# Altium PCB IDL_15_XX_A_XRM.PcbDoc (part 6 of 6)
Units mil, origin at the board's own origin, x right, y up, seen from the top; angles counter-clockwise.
Board outline 6653.34 x 6653.34 mil, 6 copper layers (Top Layer - SIG1, Layer 2 - GND1, Layer 3 - PWR, Layer 4 - PWR, Layer 5 - GND2, Bottom Layer - SIG4), stack 59.843 mil thick; 613 components, 324 nets, 1673 pads, 2316 vias.
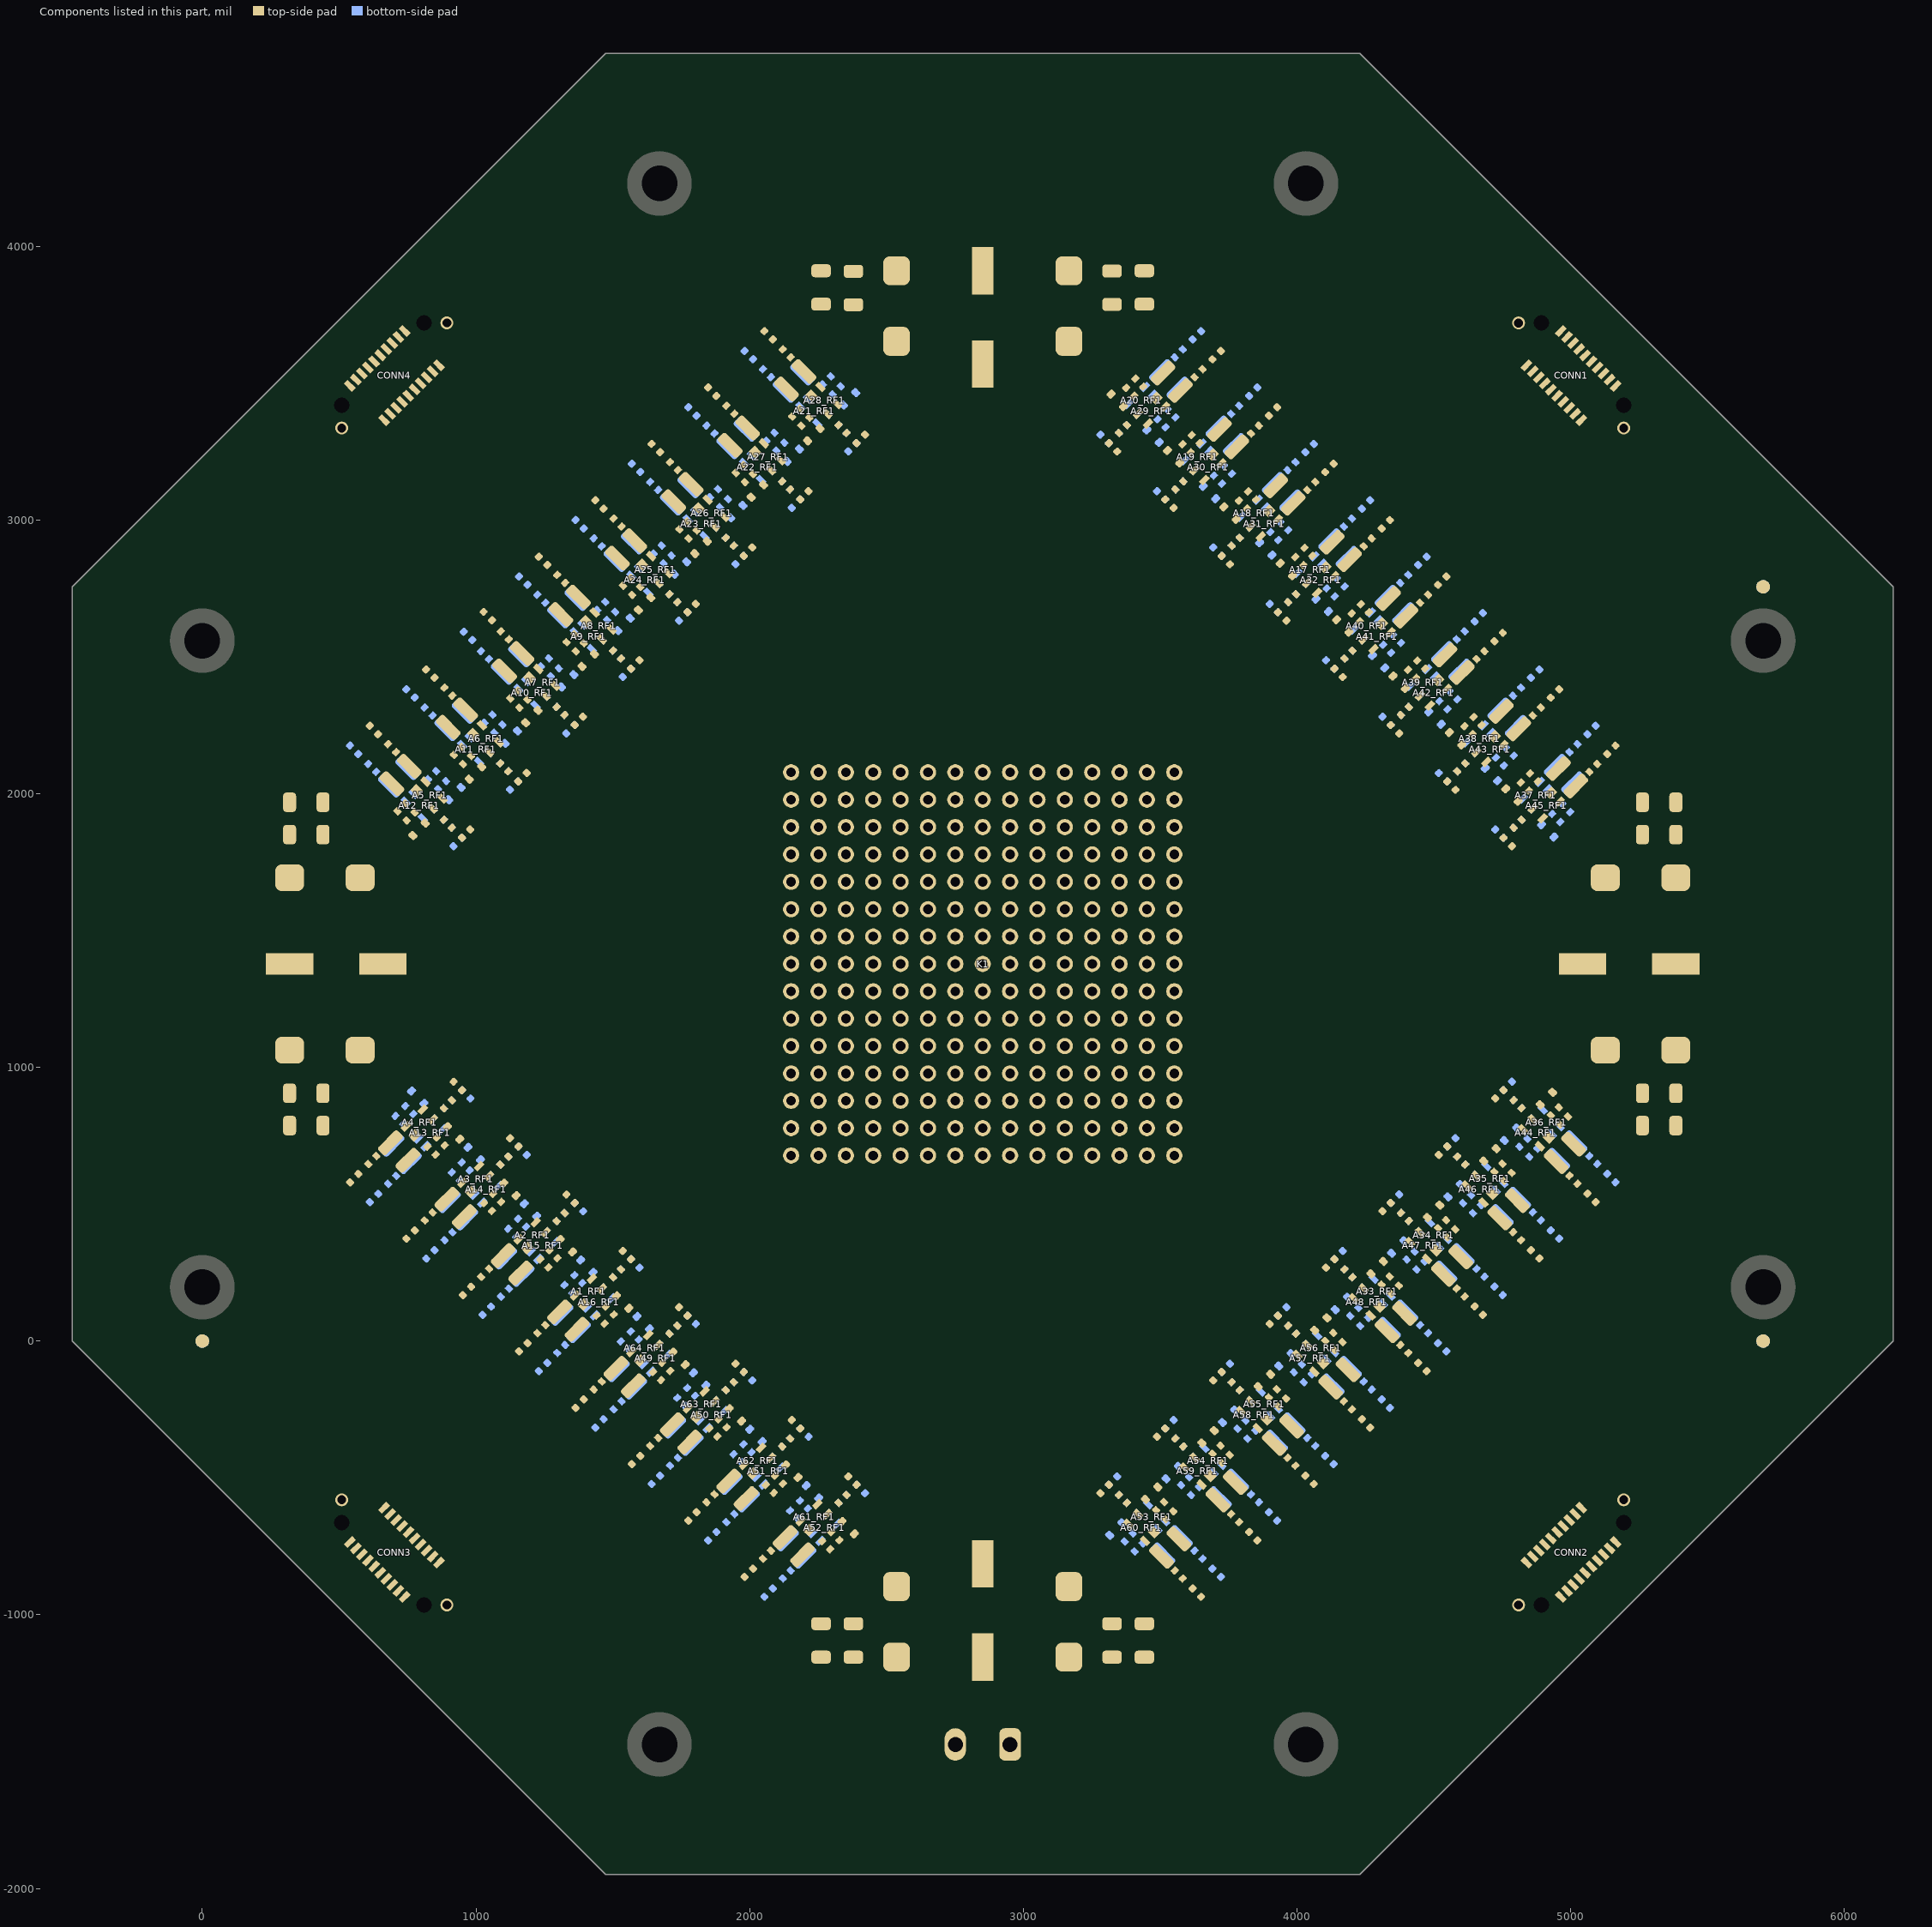
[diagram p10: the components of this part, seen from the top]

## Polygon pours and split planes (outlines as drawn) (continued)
GND on Bottom Layer - SIG4 "L2-GND" (solid, remove dead copper, pour order 38): 1473.48,4704.63 4229.39,4704.63 6178.11,2755.91 6178.11,7.87 6178.11,0 6178.1,0 4229.39,-1948.72 1473.48,-1948.72 -475.24,0 -475.24,2755.9 -475.24,2755.91
GND on Layer 2 - GND1 (split plane): 6158.01,2747.58 6158.01,8.33 4221.06,-1928.62 1481.8,-1928.62 -455.14,8.33 -455.14,2747.58 1481.8,4684.53 4221.06,4684.53
BIAS-DB on Layer 3 - PWR (split plane): 5697.77,2556.94 5697.77,198.96 4030.42,-1468.38 1672.44,-1468.38 5.1,198.96 5.1,2556.16 4.97,2556.81 1670.33,4222.18 2446.34,3446.17 2446.34,2077.95 2446.34,523.03 2446.72,521.08 2447.83,519.43 2449.48,518.32 2451.43,517.93 3251.43,517.93 3253.38,518.32 3255.04,519.43 3256.14,521.08 3256.53,523.03 3256.53,3446.17 4032.54,4222.18
BIAS-DB on Layer 3 - PWR (split plane): 6158.01,2747.58 6158.01,8.33 4221.06,-1928.62 1481.8,-1928.62 -455.14,8.33 -455.14,2747.58 1481.8,4684.53 4221.06,4684.53
3V3 on Layer 4 - PWR (split plane): 6158.01,2747.58 6158.01,8.33 4221.06,-1928.62 1481.8,-1928.62 -455.14,8.33 -455.14,2747.58 1481.8,4684.53 4221.06,4684.53
GND on Layer 5 - GND2 (split plane): 6158.01,2747.58 6158.01,8.33 4221.06,-1928.62 1481.8,-1928.62 -455.14,8.33 -455.14,2747.58 1481.8,4684.53 4221.06,4684.53

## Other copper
Top Layer - SIG1:
  region net GND: 4306.06,2568.88 4306.06,2595.33 4333.9,2623.17 4276.83,2680.24 4142.51,2545.91 4160.6,2527.82 4248.3,2615.51 4283.79,2580.02 4283.79,2557.75 4164.78,2438.73 4209.32,2394.19 4306.06,2490.93
  region net GND: 4512.07,2362.87 4512.07,2389.32 4539.91,2417.16 4482.84,2474.23 4348.52,2339.91 4366.61,2321.81 4454.3,2409.5 4489.8,2374.01 4489.8,2351.74 4370.79,2232.73 4415.33,2188.18 4512.07,2284.93
  region net GND: 4718.08,2156.87 4718.08,2183.31 4745.92,2211.15 4688.85,2268.22 4554.52,2133.9 4572.62,2115.8 4660.31,2203.5 4695.81,2168 4695.81,2145.73 4576.79,2026.72 4621.34,1982.18 4718.08,2078.92
  region net GND: 4924.08,1950.86 4924.08,1977.31 4951.92,2005.14 4894.85,2062.21 4760.53,1927.89 4778.63,1909.8 4866.32,1997.49 4901.81,1961.99 4901.81,1939.72 4782.8,1820.71 4827.34,1776.17 4924.08,1873.27
  region net GND: 4866.62,747.39 4893.07,747.39 4920.91,719.55 4977.98,776.62 4843.66,910.94 4825.56,892.85 4913.25,805.16 4877.76,769.66 4855.49,769.66 4736.48,888.67 4691.93,844.13 4788.68,747.39
  region net GND: 4660.62,541.38 4687.06,541.38 4714.9,513.54 4771.97,570.61 4637.65,704.93 4619.55,686.84 4707.25,599.15 4671.75,563.65 4649.48,563.65 4530.47,682.66 4485.93,638.12 4582.67,541.38
  region net GND: 4454.61,335.37 4481.06,335.37 4508.89,307.54 4565.96,364.6 4431.64,498.93 4413.55,480.83 4501.24,393.14 4465.74,357.65 4443.47,357.65 4324.46,476.66 4279.92,432.11 4376.66,335.37
  region net GND: 4248.6,129.37 4275.05,129.37 4302.89,101.53 4359.96,158.6 4225.63,292.92 4207.54,274.82 4295.23,187.13 4259.74,151.64 4237.47,151.64 4118.45,270.65 4073.91,226.11 4170.65,129.37
  region net GND: 4042.56,-76.67 4069.01,-76.67 4096.85,-104.51 4153.92,-47.44 4019.59,86.88 4001.5,68.78 4089.19,-18.91 4053.7,-54.4 4031.42,-54.4 3912.41,64.61 3867.87,20.07 3964.61,-76.67
  region net GND: 3836.52,-282.71 3862.97,-282.71 3890.8,-310.55 3947.87,-253.48 3813.55,-119.16 3795.46,-137.26 3883.15,-224.95 3847.65,-260.44 3825.38,-260.44 3706.37,-141.43 3661.83,-185.97 3758.57,-282.71
  region net GND: 3630.51,-488.72 3656.96,-488.72 3684.8,-516.56 3741.87,-459.49 3607.54,-325.17 3589.45,-343.26 3677.14,-430.96 3641.65,-466.45 3619.38,-466.45 3500.36,-347.44 3455.82,-391.98 3552.56,-488.72
  region net GND: 3424.5,-694.73 3450.95,-694.73 3478.79,-722.57 3535.86,-665.5 3401.54,-531.18 3383.44,-549.27 3471.13,-636.96 3435.64,-672.46 3413.37,-672.46 3294.36,-553.45 3249.82,-597.99 3346.56,-694.73
  region net GND: 2221,-637.27 2221,-663.72 2193.16,-691.56 2250.23,-748.63 2384.55,-614.3 2366.45,-596.21 2278.76,-683.9 2243.27,-648.41 2243.27,-626.14 2362.28,-507.12 2317.74,-462.58 2221,-559.32
  region net GND: 2014.99,-431.26 2014.99,-457.71 1987.15,-485.55 2044.22,-542.62 2178.54,-408.3 2160.45,-390.2 2072.75,-477.89 2037.26,-442.4 2037.26,-420.13 2156.27,-301.12 2111.73,-256.58 2014.99,-353.32
  region net GND: 1808.98,-225.26 1808.98,-251.7 1781.14,-279.54 1838.21,-336.61 1972.53,-202.29 1954.44,-184.19 1866.75,-271.89 1831.25,-236.39 1831.25,-214.12 1950.26,-95.11 1905.72,-50.57 1808.98,-147.31
  region net GND: 1602.94,-19.22 1602.94,-45.66 1575.1,-73.5 1632.17,-130.57 1766.49,3.75 1748.4,21.85 1660.71,-65.85 1625.21,-30.35 1625.21,-8.08 1744.22,110.93 1699.68,155.47 1602.94,58.73
  region net GND: 1396.9,186.83 1396.9,160.38 1369.06,132.54 1426.13,75.47 1560.45,209.79 1542.36,227.89 1454.67,140.2 1419.17,175.69 1419.17,197.96 1538.18,316.97 1493.64,361.51 1396.9,264.77
  region net GND: 1191.25,392.48 1191.25,366.03 1163.41,338.19 1220.48,281.12 1354.8,415.44 1336.71,433.54 1249.01,345.85 1213.52,381.34 1213.52,403.61 1332.53,522.62 1287.99,567.17 1191.25,470.43
  region net GND: 985.24,598.48 985.24,572.04 957.4,544.2 1014.47,487.13 1148.79,621.45 1130.7,639.55 1043.01,551.85 1007.51,587.35 1007.51,609.62 1126.52,728.63 1081.98,773.17 985.24,676.43
  region net GND: 779.23,804.49 779.23,778.04 751.39,750.21 808.46,693.14 942.79,827.46 924.69,845.55 837,757.86 801.5,793.36 801.5,815.63 920.52,934.64 875.97,979.18 779.23,882.44
  region net GND: 836.24,2008.52 809.8,2008.52 781.96,2036.36 724.89,1979.29 859.21,1844.96 877.31,1863.06 789.61,1950.75 825.11,1986.25 847.38,1986.25 966.39,1867.23 1010.93,1911.78 914.19,2008.52
  region net GND: 1042.25,2214.52 1015.8,2214.52 987.96,2242.36 930.9,2185.29 1065.22,2050.97 1083.31,2069.07 995.62,2156.76 1031.12,2192.25 1053.39,2192.25 1172.4,2073.24 1216.94,2117.78 1120.2,2214.52
  region net GND: 1248.26,2420.53 1221.81,2420.53 1193.97,2448.37 1136.9,2391.3 1271.23,2256.98 1289.32,2275.07 1201.63,2362.77 1237.12,2398.26 1259.39,2398.26 1378.41,2279.25 1422.95,2323.79 1326.21,2420.53
  region net GND: 1454.27,2626.54 1427.82,2626.54 1399.98,2654.38 1342.91,2597.31 1477.23,2462.99 1495.33,2481.08 1407.64,2568.77 1443.13,2604.27 1465.4,2604.27 1584.41,2485.26 1628.95,2529.8 1532.22,2626.54
  region net GND: 1660.31,2832.58 1633.86,2832.58 1606.02,2860.42 1548.95,2803.35 1683.27,2669.03 1701.37,2687.12 1613.68,2774.81 1649.17,2810.31 1671.44,2810.31 1790.45,2691.3 1835,2735.84 1738.26,2832.58
  region net GND: 1866.31,3038.59 1839.87,3038.59 1812.03,3066.43 1754.96,3009.36 1889.28,2875.03 1907.38,2893.13 1819.68,2980.82 1855.18,3016.32 1877.45,3016.32 1996.46,2897.31 2041,2941.85 1944.26,3038.59
  region net GND: 2072.32,3244.6 2045.88,3244.6 2018.04,3272.43 1960.97,3215.36 2095.29,3081.04 2113.38,3099.14 2025.69,3186.83 2061.19,3222.32 2083.46,3222.32 2202.47,3103.31 2247.01,3147.86 2150.27,3244.6
  region net GND: 2278.33,3450.6 2251.88,3450.6 2224.04,3478.44 2166.97,3421.37 2301.3,3287.05 2319.39,3305.14 2231.7,3392.84 2267.19,3428.33 2289.47,3428.33 2408.48,3309.32 2453.02,3353.86 2356.28,3450.6
  region net GND: 3482,3392.94 3482,3419.39 3509.84,3447.23 3452.77,3504.3 3318.45,3369.98 3336.54,3351.88 3424.23,3439.57 3459.73,3404.08 3459.73,3381.81 3340.72,3262.8 3385.26,3218.26 3484.25,3317.25
  region net GND: 3688.01,3186.94 3688.01,3213.38 3715.84,3241.22 3658.77,3298.29 3524.45,3163.97 3542.55,3145.88 3630.24,3233.57 3665.73,3198.07 3665.73,3175.8 3546.72,3056.79 3591.27,3012.25 3690.26,3111.24
  region net GND: 3894.01,2980.93 3894.01,3007.38 3921.85,3035.22 3864.78,3092.29 3730.46,2957.96 3748.55,2939.87 3836.25,3027.56 3871.74,2992.07 3871.74,2969.79 3752.73,2850.78 3797.27,2806.24 3896.27,2905.24
  region net GND: 4100.02,2774.92 4100.02,2801.37 4127.86,2829.21 4070.79,2886.28 3936.47,2751.96 3954.56,2733.86 4042.25,2821.55 4077.75,2786.06 4077.75,2763.79 3958.74,2644.78 4003.28,2600.23 4100.02,2696.97
Bottom Layer - SIG4:
  region net GND: 1603.24,2775.51 1603.24,2801.96 1575.4,2829.8 1632.47,2886.87 1766.79,2752.54 1748.7,2734.45 1661,2822.14 1625.51,2786.65 1625.51,2764.37 1744.52,2645.36 1699.98,2600.82 1603.24,2697.56
  region net GND: 1809.24,2981.52 1809.24,3007.96 1781.41,3035.8 1838.48,3092.87 1972.8,2958.55 1954.7,2940.46 1867.01,3028.15 1831.52,2992.65 1831.52,2970.38 1950.53,2851.37 1905.98,2806.83 1809.24,2903.57
  region net GND: 2015.25,3187.53 2015.25,3213.97 1987.41,3241.81 2044.48,3298.88 2178.81,3164.56 2160.71,3146.46 2073.02,3234.16 2037.52,3198.66 2037.52,3176.39 2156.53,3057.38 2111.99,3012.84 2015.25,3109.58
  region net GND: 2221.26,3393.53 2221.26,3419.98 2193.42,3447.82 2250.49,3504.89 2384.81,3370.57 2366.72,3352.47 2279.03,3440.16 2243.53,3404.67 2243.53,3382.4 2362.54,3263.39 2318,3218.84 2221.26,3315.58
  region net GND: 3424.93,3450.01 3451.38,3450.01 3479.21,3477.85 3536.28,3420.78 3401.96,3286.46 3383.87,3304.56 3471.56,3392.25 3436.06,3427.74 3413.79,3427.74 3294.78,3308.73 3250.24,3353.27 3346.98,3450.01
  region net GND: 3630.94,3244.01 3657.38,3244.01 3685.22,3271.85 3742.29,3214.78 3607.97,3080.45 3589.87,3098.55 3677.57,3186.24 3642.07,3221.74 3619.8,3221.74 3500.79,3102.72 3456.25,3147.27 3552.99,3244.01
  region net GND: 3836.94,3038 3863.39,3038 3891.23,3065.84 3948.3,3008.77 3813.98,2874.45 3795.88,2892.54 3883.57,2980.23 3848.08,3015.73 3825.81,3015.73 3706.8,2896.72 3662.25,2941.26 3758.99,3038
  region net GND: 4042.95,2831.99 4069.4,2831.99 4097.24,2859.83 4154.31,2802.76 4019.98,2668.44 4001.89,2686.53 4089.58,2774.23 4054.09,2809.72 4031.82,2809.72 3912.8,2690.71 3868.26,2735.25 3965,2831.99
  region net GND: 4248.99,2625.95 4275.44,2625.95 4303.28,2653.79 4360.35,2596.72 4226.02,2462.4 4207.93,2480.49 4295.62,2568.19 4260.13,2603.68 4237.86,2603.68 4118.84,2484.67 4074.3,2529.21 4171.04,2625.95
  region net GND: 4455,2419.94 4481.45,2419.94 4509.28,2447.78 4566.35,2390.71 4432.03,2256.39 4413.94,2274.49 4501.63,2362.18 4466.13,2397.67 4443.86,2397.67 4324.85,2278.66 4280.31,2323.2 4377.05,2419.94
  region net GND: 4661.01,2213.94 4687.45,2213.94 4715.29,2241.77 4772.36,2184.71 4638.04,2050.38 4619.94,2068.48 4707.64,2156.17 4672.14,2191.66 4649.87,2191.66 4530.86,2072.65 4486.32,2117.2 4583.06,2213.94
  region net GND: 4867.01,2007.93 4893.46,2007.93 4921.3,2035.77 4978.37,1978.7 4844.05,1844.38 4825.95,1862.47 4913.64,1950.16 4878.15,1985.66 4855.88,1985.66 4736.87,1866.65 4692.33,1911.19 4789.07,2007.93
  region net GND: 4923.69,804.46 4923.69,778.01 4951.53,750.17 4894.46,693.1 4760.14,827.43 4778.24,845.52 4865.93,757.83 4901.42,793.32 4901.42,815.59 4782.41,934.61 4826.95,979.15 4923.69,882.41
  region net GND: 4717.69,598.45 4717.69,572 4745.52,544.17 4688.45,487.1 4554.13,621.42 4572.23,639.51 4659.92,551.82 4695.41,587.32 4695.41,609.59 4576.4,728.6 4620.95,773.14 4717.69,676.4
  region net GND: 4511.68,392.44 4511.68,366 4539.52,338.16 4482.45,281.09 4348.12,415.41 4366.22,433.51 4453.91,345.81 4489.41,381.31 4489.41,403.58 4370.4,522.59 4414.94,567.13 4511.68,470.39
  region net GND: 4305.67,186.44 4305.67,159.99 4333.51,132.15 4276.44,75.08 4142.12,209.4 4160.21,227.5 4247.9,139.81 4283.4,175.3 4283.4,197.57 4164.39,316.58 4208.93,361.13 4305.67,264.39
  region net GND: 4099.63,-19.6 4099.63,-46.05 4127.47,-73.89 4070.4,-130.96 3936.08,3.36 3954.17,21.46 4041.86,-66.23 4077.36,-30.74 4077.36,-8.47 3958.35,110.54 4002.89,155.08 4099.63,58.35
  region net GND: 3893.59,-225.64 3893.59,-252.09 3921.43,-279.93 3864.36,-337 3730.04,-202.68 3748.13,-184.58 3835.82,-272.27 3871.32,-236.78 3871.32,-214.51 3752.31,-95.5 3796.85,-50.96 3893.59,-147.7
  region net GND: 3687.58,-431.65 3687.58,-458.1 3715.42,-485.94 3658.35,-543.01 3524.03,-408.69 3542.12,-390.59 3629.82,-478.28 3665.31,-442.79 3665.31,-420.52 3546.3,-301.51 3590.84,-256.96 3687.58,-353.7
  region net GND: 3481.57,-637.66 3481.57,-664.11 3509.41,-691.95 3452.34,-749.02 3318.02,-614.69 3336.12,-596.6 3423.81,-684.29 3459.3,-648.8 3459.3,-626.52 3340.29,-507.51 3384.83,-462.97 3481.57,-559.71
  region net GND: 2278.07,-694.34 2251.62,-694.34 2223.78,-722.18 2166.71,-665.11 2301.03,-530.79 2319.13,-548.88 2231.44,-636.58 2266.93,-672.07 2289.2,-672.07 2408.21,-553.06 2452.76,-597.6 2356.02,-694.34
  region net GND: 2072.06,-488.33 2045.61,-488.33 2017.77,-516.17 1960.7,-459.1 2095.03,-324.78 2113.12,-342.88 2025.43,-430.57 2060.92,-466.06 2083.19,-466.06 2202.21,-347.05 2246.75,-391.59 2150.01,-488.33
  region net GND: 1866.05,-282.33 1839.6,-282.33 1811.77,-310.16 1754.7,-253.1 1889.02,-118.77 1907.11,-136.87 1819.42,-224.56 1854.92,-260.05 1877.19,-260.05 1996.2,-141.04 2040.74,-185.59 1944.33,-282.33
  region net GND: 1660.01,-76.28 1633.56,-76.28 1605.72,-104.12 1548.65,-47.05 1682.98,87.27 1701.07,69.17 1613.38,-18.52 1648.87,-54.01 1671.15,-54.01 1790.16,65 1834.7,20.46 1738.2,-76.28
  region net GND: 1453.97,129.76 1427.52,129.76 1399.68,101.92 1342.61,158.99 1476.94,293.31 1495.03,275.21 1407.34,187.52 1442.83,152.03 1465.11,152.03 1584.12,271.04 1628.66,226.5 1531.92,129.76
  region net GND: 1248.32,335.41 1221.87,335.41 1194.03,307.57 1136.96,364.64 1271.29,498.96 1289.38,480.86 1201.69,393.17 1237.18,357.68 1259.45,357.68 1378.47,476.69 1423.01,432.15 1326.27,335.41
  region net GND: 1042.31,541.41 1015.86,541.41 988.03,513.58 930.96,570.65 1065.28,704.97 1083.37,686.87 995.68,599.18 1031.18,563.69 1053.45,563.69 1172.46,682.7 1217,638.15 1120.26,541.41
  region net GND: 834.89,748.84 808.44,748.84 780.6,721 723.53,778.07 857.86,912.39 875.95,894.29 788.26,806.6 823.75,771.11 846.02,771.11 965.04,890.12 1009.58,845.58 912.84,748.84
  region net GND: 779.17,1951.45 779.17,1977.89 751.33,2005.73 808.4,2062.8 942.73,1928.48 924.63,1910.38 836.94,1998.08 801.44,1962.58 801.44,1940.31 920.46,1821.3 875.91,1776.76 779.17,1873.5
  region net GND: 985.18,2157.45 985.18,2183.9 957.34,2211.74 1014.41,2268.81 1148.73,2134.49 1130.64,2116.39 1042.95,2204.08 1007.45,2168.59 1007.45,2146.32 1126.46,2027.31 1081.92,1982.77 985.18,2079.51
  region net GND: 1191.19,2363.46 1191.19,2389.91 1163.35,2417.75 1220.42,2474.82 1354.74,2340.49 1336.65,2322.4 1248.95,2410.09 1213.46,2374.6 1213.46,2352.33 1332.47,2233.32 1287.93,2188.77 1191.19,2285.51
  region net GND: 1397.2,2569.47 1397.2,2595.92 1369.36,2623.76 1426.43,2680.82 1560.75,2546.5 1542.65,2528.41 1454.96,2616.1 1419.47,2580.61 1419.47,2558.33 1538.48,2439.32 1493.94,2394.78 1397.2,2491.52
Layer 3 - PWR (plane layer: these items are gaps in the copper):
  lines w10: 0,2556.16 0,196.85 1670.33,-1473.48 4032.54,-1473.48 5702.87,196.85 5702.87,2559.06 4032.54,4229.39 3251.43,3448.28 3251.43,523.03 2451.43,523.03 2451.43,2077.95 2451.43,3448.28 1670.33,4229.39 0,2559.06

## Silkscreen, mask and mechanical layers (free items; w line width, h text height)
Top Overlay:
  text "IDL_15_037 / XRM_PreAMP_Board Rev.A / Designer: LVV, PO" at 1347.5,-1948.82 h60
Bottom Overlay:
  text "IDL_15_037 / XRM_PreAMP_Board Rev.A / Designer: LVV, PO" at 4237.26,-1948.82 h60
Board Outline:
  the board outline again, w10
Sheet Top:
  lines w3.9: -1830.16,-6167.66 13969.75,-6167.66 13969.75,5312.24 -1830.16,5312.24 -1830.16,-6167.66 ; -1729.9,-6067.95 13869.49,-6067.95 13869.49,5212.54 -1729.9,5212.54 -1729.9,-6067.95
  lines w3.94: 7179.84,-6067.95 7179.84,-5357.76 13869.49,-5357.76 ; 7179.84,-5716.99 13869.84,-5716.99 ; 7179.84,-5597.76 11999.84,-5597.76 ; 7179.84,-5477.76 11999.84,-5477.76 ; 8684.84,-5716.99 8684.84,-5357.76 ; 9684.84,-5716.99 9684.84,-5357.76 ; 11274.84,-5716.99 11274.84,-5357.76 ; 11999.84,-6067.95 11999.84,-5357.76 ; 11999.84,-5537.76 13869.49,-5537.76
  text "Designer:" at 7204.84,-5447.76 h100
  text ".Designer" at 7769.84,-5452.76 h100
  text "Revision:" at 8709.84,-5452.76 h100
  text ".Version" at 9269.84,-5452.76 h100
  text "File:" at 9709.84,-5452.76 h100
  text ".Pcb_File_Name_No_Path" at 9909.84,-5452.76 h100
  text "Sheet  1 of  1" at 11304.84,-5452.76 h100
  text "Code:" at 12024.84,-5497.76 h100
  text "Drawn By:" at 7204.84,-5567.76 h100
  text ".Drawn_By" at 7769.84,-5567.76 h100
  text "Modif. Date:" at 8709.84,-5572.76 h100
  text "Date" at 9214.84,-5572.76 h100
  text "Variant:" at 9709.84,-5572.76 h100
  text ".VariantName" at 10074.84,-5572.76 h100
  text "ID:" at 12029.84,-5677.76 h100
  text "Approved By:" at 7204.84,-5687.76 h100
  text ".Approved_By" at 7769.84,-5687.76 h100
  text "Print Date:" at 8709.84,-5692.76 h100
  text ".Print_Date" at 9214.84,-5692.76 h100
  text "Signature:" at 9709.84,-5692.76 h100
  text "Size:  A3 H" at 11304.84,-5692.76 h100
  text "Title:" at 7204.84,-5817.76 h100
  text "University of Hawaii at Manoa" at 12031.26,-5826.02 h100
  text "High Energy Physics Group" at 12031.26,-5924.45 h100
  text ".Printout_Name" at 7429.84,-5957.76 h100
  text "Instrumentation Development Laboratory" at 12031.26,-6026.81 h100
Sheet Bot:
  lines w3.9: -1830.42,-6167.46 -1830.42,5312.44 13969.49,5312.44 13969.49,-6167.46 -1830.42,-6167.46 ; -1730.16,-6067.76 -1730.16,5212.74 13869.23,5212.74 13869.23,-6067.76 -1730.16,-6067.76
  lines w3.94: -1730.51,-5716.8 4959.49,-5716.8 ; -1730.16,-5537.56 139.49,-5537.56 ; -1730.16,-5357.56 4959.49,-5357.56 4959.49,-6067.76 ; 139.49,-6067.76 139.49,-5357.56 ; 139.49,-5597.56 4959.49,-5597.56 ; 139.49,-5477.56 4959.49,-5477.56 ; 864.49,-5716.8 864.49,-5357.56 ; 2454.49,-5716.8 2454.49,-5357.56 ; 3454.49,-5716.8 3454.49,-5357.56
  text "Designer:" at 4934.49,-5447.56 h100
  text "Sheet  1 of  1" at 834.49,-5452.56 h100
  text ".Pcb_File_Name_No_Path" at 2229.49,-5452.56 h100
  text "File:" at 2429.49,-5452.56 h100
  text ".Version" at 2869.49,-5452.56 h100
  text "Revision:" at 3429.49,-5452.56 h100
  text ".Designer" at 4369.49,-5452.56 h100
  text "Code:" at 114.49,-5497.56 h100
  text ".Drawn_By" at 4369.49,-5567.56 h100
  text "Drawn By:" at 4934.49,-5567.56 h100
  text ".VariantName" at 2064.49,-5572.56 h100
  text "Variant:" at 2429.49,-5572.56 h100
  text "Date" at 2924.49,-5572.56 h100
  text "Modif. Date:" at 3429.49,-5572.56 h100
  text "ID:" at 109.49,-5677.56 h100
  text ".Approved_By" at 4369.49,-5687.56 h100
  text "Approved By:" at 4934.49,-5687.56 h100
  text "Size:  A3 H" at 834.49,-5692.56 h100
  text "Signature:" at 2429.49,-5692.56 h100
  text ".Print_Date" at 2924.49,-5692.56 h100
  text "Print Date:" at 3429.49,-5692.56 h100
  text "Title:" at 4934.49,-5817.56 h100
  text "University of Hawaii at Manoa" at 106.14,-5829.97 h100
  text "High Energy Physics Group" at 106.14,-5928.39 h100
  text ".Printout_Name" at 4709.49,-5957.56 h100
  text "Instrumentation Development Laboratory" at 106.14,-6030.75 h100
FabNTop:
  text ".IDLnum" at 12324.84,-5497.76 h100
  text "ASSEMBLY" at 11304.88,-5574.05 h100
  text ".BoardName" at 12324.84,-5677.76 h100
FabNBot:
  text ".IDLnum" at -185.51,-5497.56 h100
  text "ASSEMBLY" at 834.41,-5574.05 h100
  text ".BoardName" at -185.51,-5677.56 h100
PCBNTop:
  lines w10: 0,2556.16 0,2559.06
  text ".IDLnum" at 12324.84,-5497.76 h100
  text "PCB" at 11304.88,-5574.05 h100
  text ".BoardName" at 12324.84,-5677.76 h100
PCBNBot:
  text ".IDLnum" at -185.28,-5497.28 h100
  text "PCB" at 834.41,-5574.05 h100
  text ".BoardName" at -185.51,-5677.56 h100
CompC:
  lines w10: -475.14,1377.85 6178.2,1377.85 ; 0,-193.95 0,196.85 ; 91.59,0 -475.24,0 ; 193.95,688.98 2162.34,-1279.41 ; 194.07,2067.05 2162.46,4035.43 ; 318.95,682.99 318.95,1377.95 ; 456.24,630.4 873.92,1048.08 ; 499.12,-974.46 701.53,-772.05 ; 897.58,282.36 897.58,2473.59 ; 897.58,1377.98 -77.7,1377.98 6178.18,1377.98 ; 1448.48,2780.9 701.43,3527.96 1669.56,2559.83 1800.72,2428.67 ; 1448.58,-25 701.52,-772.05 ; 1473.48,400.59 1473.48,2467.52 ; 1566.54,2456.81 1772.58,2662.85 ; 1566.63,299.1 1772.67,93.06 ; 1621.12,1377.95 1473.48,1377.95 2851.43,1377.95 ; 1704.49,230.92 1669.65,196.08 701.52,-772.05 ; 1755.29,3331.81 3947.02,3331.81 ; 1755.5,-575.91 3947.37,-575.91 ; 1780.91,0 3847.84,0 ; 1817.97,2755.91 4248.09,2755.91 ; 2156.47,-1154.53 2851.43,-1154.53 3511.33,-1154.53 ; 2156.47,3910.43 2851.43,3910.43 ; 2511.43,-610.34 2540.66,-581.11 ; 2851.43,-1948.72 2851.43,4704.63 ; 2851.43,-1473.48 2851.43,4834.65 ; 2851.43,0 2851.43,1377.95 ; 2851.43,2755.91 2851.43,1377.95 ; 3125.98,-622.48 3540.41,-1036.91 ; 3167.73,3341.75 3191.78,3365.8 ; 3407.09,3581.51 3819.89,3994.3 ; 3540.41,-1279.53 5508.8,688.86 ; 3540.53,4035.32 5508.91,2066.93 ; 3930.29,93.06 4136.33,299.1 ; 3930.29,2662.65 4136.33,2456.61 ; 3944.8,2471.12 4033.31,2559.63 5001.44,3527.76 5203.85,3730.17 ; 3982.29,247.09 4033.31,196.08 5001.44,-772.05 4254.39,-25 ; 4229.39,-77.83 4229.39,2411.42 ; 4229.39,1377.95 2851.43,1377.95 ; 4806.28,282.33 4806.28,2473.58 ; 5050.17,826.97 5467.81,409.33 ; 5383.91,2072.91 5383.91,1377.95 ; 5434.11,2755.91 6178.11,2755.91 ; 5663.4,0 6178.11,0 ; 5702.87,-317.86 5702.87,196.85 ; 5702.87,2559.06 5702.87,2906.55 ; -475.24,0 -475.24,196.85 0,196.85 ; -475.24,0 -336.04,-139.19 0,196.85 ; 318.95,1377.95 318.95,718.05 318.95,1377.95 ; 318.95,1377.95 318.95,2072.91 ; 318.95,1377.95 318.95,2072.91 ; 318.95,1377.95 318.95,2072.91 ; 2851.43,3910.43 2191.54,3910.43 2851.43,3910.43 ; 2851.43,3910.43 3546.39,3910.43 ; 2851.43,3910.43 3546.39,3910.43 ; 2851.43,3910.43 3546.39,3910.43 ; 5383.91,682.99 5383.91,1377.95 ; 5383.91,682.99 5383.91,1377.95 ; 5383.91,682.99 5383.91,1377.95 ; 5383.91,1377.95 5383.91,2037.85 5383.91,1377.95
Drill Drawing:
  drawing of 537 lines, arcs and shapes, not listed
  text "Notes:" at 8013.05,3945.06 h100
  text "1. Board shall be fabricated - performace class II as per IPC-6011 and IPC6012" at 8013.05,3820.06 h100
  text "2. PCB manufacturer logo, P/N, revision and/or date code of manufacturing" at 8013.05,3695.06 h100
  text "shall be printed in top solder mask (not over pcb traces, allowed over copper plane)." at 8113.05,3595.06 h100
  text "The date code shall be in the format: \"WWYY\" where WW=week and YY= year, max height 0.15 inches" at 8113.05,3495.06 h100
  text "3. Silkscreen printed on both sides" at 8013.05,3370.06 h100
  text "4. Material: high temperature FR4 class epoxy glass rated UL94V-0. UL symbol and rating shall be marked farside" at 8013.05,3245.06 h100
  text "35um copper for external and internal layers" at 8113.07,3145.06 h100
  text "Must be RoHS compliant and survive a lead-free assembly max reflow of 260 deg C (5 passes)" at 8113.05,3045.06 h100
  text "Td rating: >340 deg C" at 8163.05,2920.06 h100
  text "Tg = 150 deg C (min)" at 8167.09,2809.8 h100
  text "5. Solder mask: SMOBC per IPC-SM-840C, class T must be Rohs compliant, 0.001\" max measured over bare copper plating," at 8013.05,2570.06 h100
  text "must clear all lands as indicated on gerber solder mask layers, color= GREEN" at 8113.05,2470.06 h100
  text "6. Finish: electro-less nickel immersion gold (ENIG), 0.05-0.125um Au over 3-6um Ni - over bare copper only" at 8012.84,2316.24 h100
  text "7. Solderability test: Category 2 of J-STD-003" at 8013.05,2170.06 h100
  text "8. Finished boards shall not have nicks, scratches, voids, exposed copper, poor plating or misdrilled holes" at 8013.05,2020.06 h100
  text "9. All holes sizes are after plating" at 8013.05,1870.06 h100
  text "10. PCB manufacturer may add copper thieving as needed to improve manufacturability," at 7963.05,1720.06 h100
  text "thieving to be 0.030\" round pads at 0.050\" spacing." at 8113.05,1620.06 h100
  text "Thieving will have a minimum of 0.100\" clearance from existing copper and should not be placed under surface mounted devices" at 8113.05,1520.06 h100
  text "11. PCB manufacturer may use tear drops to improve annular rings as long as DRC rules are followed" at 7968.05,1380.06 h100
  text "12. All via connections to power and ground planes are solid" at 7968.05,1240.06 h100
  text "13. All unconnected pads on inner signal layers are removed" at 7968.05,1100.06 h100
  text "14. All finished boards are to be 100% electrically tested" at 7968.07,960.06 h100
  text "15. Unless otherwise indicated, all linear toleracnes shall be XX.X +/-0.2mm and XX.XX +/- 0.1mm" at 7968.05,820.06 h100
  text "16. Gerber file GM1 shows board outline (milling line)" at 7968.05,680.05 h100
  text "17. Table 1 shows Layer stack details" at 7968.04,540.03 h100
  text "Additional notes:" at 7973.05,275.06 h100
  text "A1. Finished board thickness = 1.6mm +/- 0.1mm; measured over top/bottom copper and solder mask" at 7973.07,135.06 h100
  text "Table 1a: Layer Stack Details for IDL_15_37 Rev.A (Metric Units)" at 7956.45,-625.24 h100
  text "Layer" at 8016.93,-785.83 h60
  text "Name" at 8268.03,-785.83 h60
  text "Material" at 8870.75,-785.83 h60
  text "Thickness" at 9307.09,-785.83 h60
  text "Constant" at 9665.42,-785.83 h60
  text "Board Layer Stack" at 9997.15,-785.83 h60
  text "Board Layer Stack" at 10554.59,-785.83 h60
  text "1" at 8016.93,-905.83 h60
  text "Top Overlay" at 8268.03,-905.83 h60
  text "2" at 8016.93,-1025.83 h60
  text "Top Solder" at 8268.03,-1025.83 h60
  text "Solder Resist" at 8870.75,-1025.83 h60
  text "0.010mm" at 9307.09,-1025.83 h60
  text "3.5" at 9665.42,-1025.83 h60
  text "3" at 8016.93,-1145.83 h60
  text "Top Layer - SIG1" at 8268.03,-1145.83 h60
  text "Copper" at 8870.75,-1145.83 h60
  text "0.035mm" at 9307.09,-1145.83 h60
  text "4" at 8016.93,-1265.83 h60
  text "Dielectric 1" at 8268.03,-1265.83 h60
  text "FR-4" at 8870.75,-1265.83 h60
  text "0.150mm" at 9307.09,-1265.83 h60
  text "4.65" at 9665.42,-1265.83 h60
  text "5" at 8016.93,-1385.83 h60
  text "Layer 2 - GND1" at 8268.03,-1385.83 h60
  text "Copper" at 8870.75,-1385.83 h60
  text "0.035mm" at 9307.09,-1385.83 h60
  text "6" at 8016.93,-1505.83 h60
  text "Dielectric 3" at 8268.03,-1505.83 h60
  text "FR-4" at 8870.75,-1505.83 h60
  text "0.430mm" at 9307.09,-1505.83 h60
  text "4.65" at 9665.42,-1505.83 h60
  text "7" at 8016.93,-1625.83 h60
  text "Layer 3 - PWR" at 8268.03,-1625.83 h60
  text "Copper" at 8870.75,-1625.83 h60
  text "0.035mm" at 9307.09,-1625.83 h60
  text "8" at 8016.93,-1745.83 h60
  text "Dielectric 6" at 8268.03,-1745.83 h60
  text "FR-4" at 8870.75,-1745.83 h60
  text "0.150mm" at 9307.09,-1745.83 h60
  text "4.65" at 9665.42,-1745.83 h60
  text "9" at 8016.93,-1865.83 h60
  text "Layer 4 - PWR" at 8268.03,-1865.83 h60
  text "Copper" at 8870.75,-1865.83 h60
  text "0.035mm" at 9307.09,-1865.83 h60
  text "10" at 8016.93,-1985.83 h60
  text "Dielectric 5" at 8268.03,-1985.83 h60
  text "FR-4" at 8870.75,-1985.83 h60
  text "0.430mm" at 9307.09,-1985.83 h60
  text "4.65" at 9665.42,-1985.83 h60
  text "11" at 8016.93,-2105.83 h60
  text "Layer 5 - GND2" at 8268.03,-2105.83 h60
  text "Copper" at 8870.75,-2105.83 h60
  text "0.035mm" at 9307.09,-2105.83 h60
  text "12" at 8016.93,-2225.83 h60
  text "Dielectric 4" at 8268.03,-2225.83 h60
  text "FR-4" at 8870.75,-2225.83 h60
  text "0.150mm" at 9307.09,-2225.83 h60
  text "4.65" at 9665.42,-2225.83 h60
  text "13" at 8016.93,-2345.83 h60
  text "Bottom Layer - SIG4" at 8268.03,-2345.83 h60
  text "Copper" at 8870.75,-2345.83 h60
  text "0.035mm" at 9307.09,-2345.83 h60
  text "14" at 8016.93,-2465.83 h60
  text "Bottom Solder" at 8268.03,-2465.83 h60
  text "Solder Resist" at 8870.75,-2465.83 h60
  text "0.010mm" at 9307.09,-2465.83 h60
  text "3.5" at 9665.42,-2465.83 h60
  text "15" at 8016.93,-2585.83 h60
  text "Bottom Overlay" at 8268.03,-2585.83 h60
  text "Symbol" at 8047.43,-3074.3 h72
  text "Count" at 8314.32,-3074.3 h72
  text "Hole Size" at 8592,-3074.3 h72
  text "Plated" at 9154.66,-3074.3 h72
  text "Hole Type" at 9387.24,-3074.3 h72
  text "Drill Layer Pair" at 9732.49,-3074.3 h72
  text "Via/Pad" at 10736.88,-3074.3 h72
  text "Pad Shape" at 11017.2,-3074.3 h72
  text "Technology" at 11387.87,-3074.3 h72
  text "2" at 8314.32,-3173.66 h60
  text "1.400mm (55.12mil)" at 8592,-3173.66 h60
  text "PTH" at 9154.66,-3173.66 h60
  text "Round" at 9387.24,-3173.66 h60
  text "Top Layer - SIG1 - Bottom Layer - SIG4" at 9732.49,-3173.66 h60
  text "Pad" at 10736.88,-3173.66 h60
  text "*" at 11017.2,-3173.66 h60
  text "Drilled" at 11387.87,-3173.66 h60
  text "8" at 8314.32,-3273.01 h60
  text "0.830mm (32.68mil)" at 8592,-3273.01 h60
  text "PTH" at 9154.66,-3273.01 h60
  text "Round" at 9387.24,-3273.01 h60
  text "Top Layer - SIG1 - Bottom Layer - SIG4" at 9732.49,-3273.01 h60
  text "Pad" at 10736.88,-3273.01 h60
  text "Rounded" at 11017.2,-3273.01 h60
  text "Drilled" at 11387.87,-3273.01 h60
  text "8" at 8314.32,-3372.36 h60
  text "1.450mm (57.09mil)" at 8592,-3372.36 h60
  text "NPTH" at 9154.66,-3372.36 h60
  text "Round" at 9387.24,-3372.36 h60
  text "Top Layer - SIG1 - Bottom Layer - SIG4" at 9732.49,-3372.36 h60
  text "Pad" at 10736.88,-3372.36 h60
  text "Rounded" at 11017.2,-3372.36 h60
  text "Drilled" at 11387.87,-3372.36 h60
  text "8" at 8314.32,-3471.72 h60
  text "3.300mm (129.92mil)" at 8592,-3471.72 h60
  text "PTH" at 9154.66,-3471.72 h60
  text "Round" at 9387.24,-3471.72 h60
  text "Top Layer - SIG1 - Bottom Layer - SIG4" at 9732.49,-3471.72 h60
  text "Pad" at 10736.88,-3471.72 h60
  text "Rounded" at 11017.2,-3471.72 h60
  text "Drilled" at 11387.87,-3471.72 h60
  text "Symbol" at 8047.43,-3571.07 h72
  text "Symbol" at 8047.43,-3571.07 h72
  text "Count" at 8314.32,-3571.07 h72
  text "Count" at 8314.32,-3571.07 h72
  text "225" at 8314.32,-3571.07 h60
  text "Hole Size" at 8591.83,-3571.07 h72
  text "0.900mm (35.43mil)" at 8592,-3571.07 h60
  text "Hole Size" at 8618.04,-3571.07 h72
  text "Plated" at 9124.63,-3571.07 h72
  text "Plated" at 9150.84,-3571.07 h72
  text "PTH" at 9154.66,-3571.07 h60
  text "Hole Type" at 9357.2,-3571.07 h72
  text "Hole Type" at 9383.41,-3571.07 h72
  text "Round" at 9387.24,-3571.07 h60
  text "Drill Layer Pair" at 9702.46,-3571.07 h72
  text "Drill Layer Pair" at 9728.67,-3571.07 h72
  text "Top Layer - SIG1 - Bottom Layer - SIG4" at 9732.49,-3571.07 h60
  text "Via/Pad" at 10586.2,-3571.07 h72
  text "Via/Pad" at 10694.57,-3571.07 h72
  text "Pad" at 10736.88,-3571.07 h60
  text "Pad Shape" at 10866.52,-3571.07 h72
  text "Pad Shape" at 10974.89,-3571.07 h72
  text "Rounded" at 11017.2,-3571.07 h60
  text "Technology" at 11237.19,-3571.07 h72
  text "Technology" at 11345.56,-3571.07 h72
  text "Drilled" at 11387.87,-3571.07 h60
  text "1069" at 8314.32,-3670.43 h60
  text "855" at 8314.32,-3670.43 h60
  text "392" at 8314.32,-3670.43 h60
  text "0.300mm (11.81mil)" at 8591.83,-3670.43 h60
  text "0.300mm (11.81mil)" at 8592,-3670.43 h60
  text "0.300mm (11.81mil)" at 8618.04,-3670.43 h60
  text "PTH" at 9124.63,-3670.43 h60
  text "PTH" at 9150.84,-3670.43 h60
  text "PTH" at 9154.66,-3670.43 h60
  text "Round" at 9357.2,-3670.43 h60
  text "Round" at 9383.41,-3670.43 h60
  text "Round" at 9387.24,-3670.43 h60
  text "Top Layer - SIG1 - Layer 2 - GND1" at 9702.46,-3670.43 h60
  text "Layer 5 - GND2 - Bottom Layer - SIG4" at 9728.67,-3670.43 h60
  text "Top Layer - SIG1 - Bottom Layer - SIG4" at 9732.49,-3670.43 h60
  text "Via" at 10586.2,-3670.43 h60
  text "Via" at 10694.57,-3670.43 h60
  text "Via" at 10736.88,-3670.43 h60
  text "Rounded" at 10866.52,-3670.43 h60
  text "Rounded" at 10974.89,-3670.43 h60
  text "Rounded" at 11017.2,-3670.43 h60
  text "Drilled" at 11237.19,-3670.43 h60
  text "Drilled" at 11345.56,-3670.43 h60
  text "Drilled" at 11387.87,-3670.43 h60
  text "1069 Total" at 8314.32,-3769.78 h60
  text "855 Total" at 8314.32,-3769.78 h60
  text "643 Total" at 8314.32,-3769.78 h60

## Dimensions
6178.11,0 to -475.24,0 on Dimensions
4229.39,-1948.72 to 1473.48,-1948.72 on Dimensions
4229.39,4704.63 to 4229.39,-1948.72 on Dimensions
6178.11,2755.91 to 6178.11,0 on Dimensions

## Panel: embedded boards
"IDL_15_XX_A_XRM.PcbDoc" at 0,0, 1 rows x 1 columns, spacing 0 x 0, rotation 0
